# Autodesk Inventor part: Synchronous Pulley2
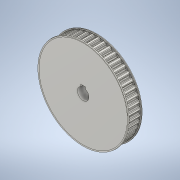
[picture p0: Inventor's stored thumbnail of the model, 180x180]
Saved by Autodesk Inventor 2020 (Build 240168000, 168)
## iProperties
Created: 2019-09
Part Number: Synchronous Pulley2
Material: Steel
Document SubType Name: Modeling
Designer: user
Density: 1 g/cm^3
Appearance: Steel
CustomPartVersion: 1
Author: user
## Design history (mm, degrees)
sketch "Pulley Sketch"
  geometry: L1 (-1.418, 38.528)-(-0.66, 36.903); L2 (-0.66, 36.903)-(0.66, 36.903); L3 (0.66, 36.903)-(1.418, 38.528); L4 (0, 0)-(0, 38.554); C1 r 38.808 at (0, 0); A1 r 38.554 centre (0, 0) between (-1.418, 38.528) and (1.418, 38.528); 2 further points
  constraints: 8 end point, 3 coincident, 3 point on circle, 2 centre point, 1 horizontal, 1 midpoint, 1 point on line, 1 vertical, 1 vertical alignment, 3 other
  dimensions: "d0" = 77.61668 diameter of C1 (computed from da_pb, da_z); "d1" = 0.254 radial gap between concentric circles of C1 A1 (= da_a); "d2" = 1.651 dimension on A1 (= da_hg); "d3" = 50 deg angle of L3 L1 (= 2 x da_fi); "d4" = 1.3208 distance of L1.end L2.end (= da_bw)
extrude "Base Body" new body sketch "Pulley Sketch" stored distance "d5" = 10.414 (= da_bf); taper "d6" = 0 deg
extrude "Tooth" cut sketch "Pulley Sketch" extent not by distance; stored distance "d7" = 10.414 (= da_bf); taper "d8" = 0 deg
fillet "Tooth Fillet" dims "d9" = 0.4064 (= da_rb), "d10" = 0.635 (= da_rt)
feature "Left flange"
feature "Right flange"
sketch "Sketch2"
  geometry: L1 (-2.03, 6.33)-(2.03, 6.33); L2 (2.03, 6.33)-(2.03, 4.569); L3 (-2.03, 4.569)-(-2.03, 6.33); A1 r 5 centre (0, 0) between (-2.03, 4.569) and (2.03, 4.569); 2 further points
  constraints: 6 end point, 2 point on circle, 1 centre point, 1 coincident, 1 horizontal, 1 midpoint, 1 parallel, 1 perpendicular, 1 vertical alignment
  dimensions: "d17" = 10 diameter of A1
extrude "Extrusion3" cut sketch "Sketch2" extent not by distance; stored distance "d18" = 0; taper "d19" = 0 deg
body "Solid1"
pattern_circular "Teeth" dims angle "d12" = 360 deg
other parameters: "da_pb" = 5.08 [user parameter; used in 1 equation term], "da_fi" = 25 deg [user parameter; used in 1 equation term], "da_hg" = 1.651 [user parameter; used in 1 equation term], "da_bw" = 1.3208 [user parameter; used in 1 equation term], "da_rb" = 0.4064 [user parameter; used in 1 equation term], "da_rt" = 0.635 [user parameter; used in 1 equation term], "da_a" = 0.254 [user parameter; used in 3 equation terms], "da_bf" = 10.414 [user parameter; used in 2 equation terms], "d15" = 0, "da_wf" = 0.7366 [user parameter; used in 2 equation terms], "da_hf" = 1.016 [user parameter; used in 2 equation terms], "d16" = 0
